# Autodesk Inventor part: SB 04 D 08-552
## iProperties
Manufacturer: Euchner
Author: jhagarty
Shininess: 64.0
Angle Display Precision: 2
Document Length Units: 11269
Document Angle Units: 11283
Document Time Units: 11279
Document Mass Units: 11290
Document Length Units Precision: 3
Document Angle Units Precision: 2
Compacted: True
PropertySet Name: _Private Model Information
Created: 2001-11
Part Number: SB 04 D 08-552
Description: Euchner Limit Switch
Document SubType Name: Modeling
Designer: jhagarty
Control State: 0
Master: False
Checked Out: False
PropertySet Name: Design Tracking Control
Density: 0.0
Volumn: 0.0
Area: 0.0
PropertySet Name: Model Information
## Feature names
1. Extrusion1
2. Hole1
3. Extrusion2
4. Extrusion3
5. Rectangular Pattern1
6. Extrusion4
7. Extrusion5
8. Extrusion6
9. Chamfer1
